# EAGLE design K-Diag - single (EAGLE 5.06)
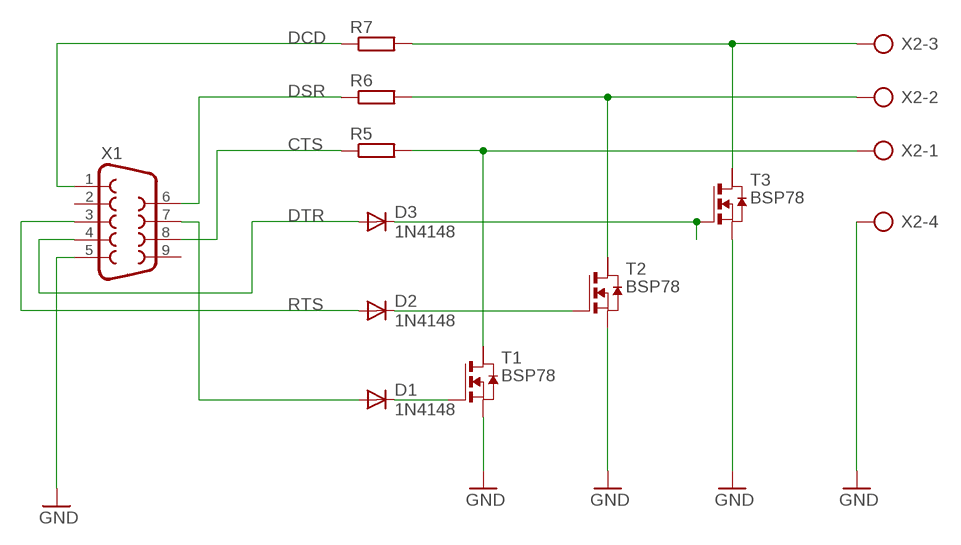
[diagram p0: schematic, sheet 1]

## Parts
D1  1N4148  1N4148DO35-7  [DO35-7]
D2  1N4148  1N4148DO35-7  [DO35-7]
D3  1N4148  1N4148DO35-7  [DO35-7]
R5  R-EU_0207/7  [0207/7]
R6  R-EU_0207/7  [0207/7]
R7  R-EU_0207/7  [0207/7]
T1  BSP78  NMOSSOT223  [SOT223]
T2  BSP78  NMOSSOT223  [SOT223]
T3  BSP78  NMOSSOT223  [SOT223]
X1  DB9FEMALE  [DB9]
X2  AK500/4  [AK500/4]

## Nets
CTS: R5.1 X1.8
DCD: R7.1 X1.1
DSR: R6.1 X1.6
DTR: D3.A X1.4
GND: T1.3(S) T2.3(S) T3.3(S) X1.5 X2.4
N$1: D3.C T3.1(G)
N$2: D2.C T2.1(G)
N$3: D1.C T1.1(G)
N$4: R5.2 T1.2(D) X2.1
N$5: R6.2 T2.2(D) X2.2
N$6: R7.2 T3.2(D) X2.3
N$7: D1.A X1.7
RTS: D2.A X1.3
Unconnected: T1.4(D2) T2.4(D2) T3.4(D2) X1.2 X1.9

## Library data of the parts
D1-D3 = diode:1N4148: DIODE
R5-R7 = rcl:R-EU_: RESISTOR, European symbol
T1-T3 = zetex:NMOSSOT223: MOS FET
X1 = SparkFun:DB9: DB9 Connector Standard DB9 (D-Sub 9) serial connector. Can be used for CAN bus as well as RS485 and RS232. Footprint production proven. Spark Fun Electronics SKU : PRT-00429
X2 = con-ptr500:AK500/4: CONNECTOR

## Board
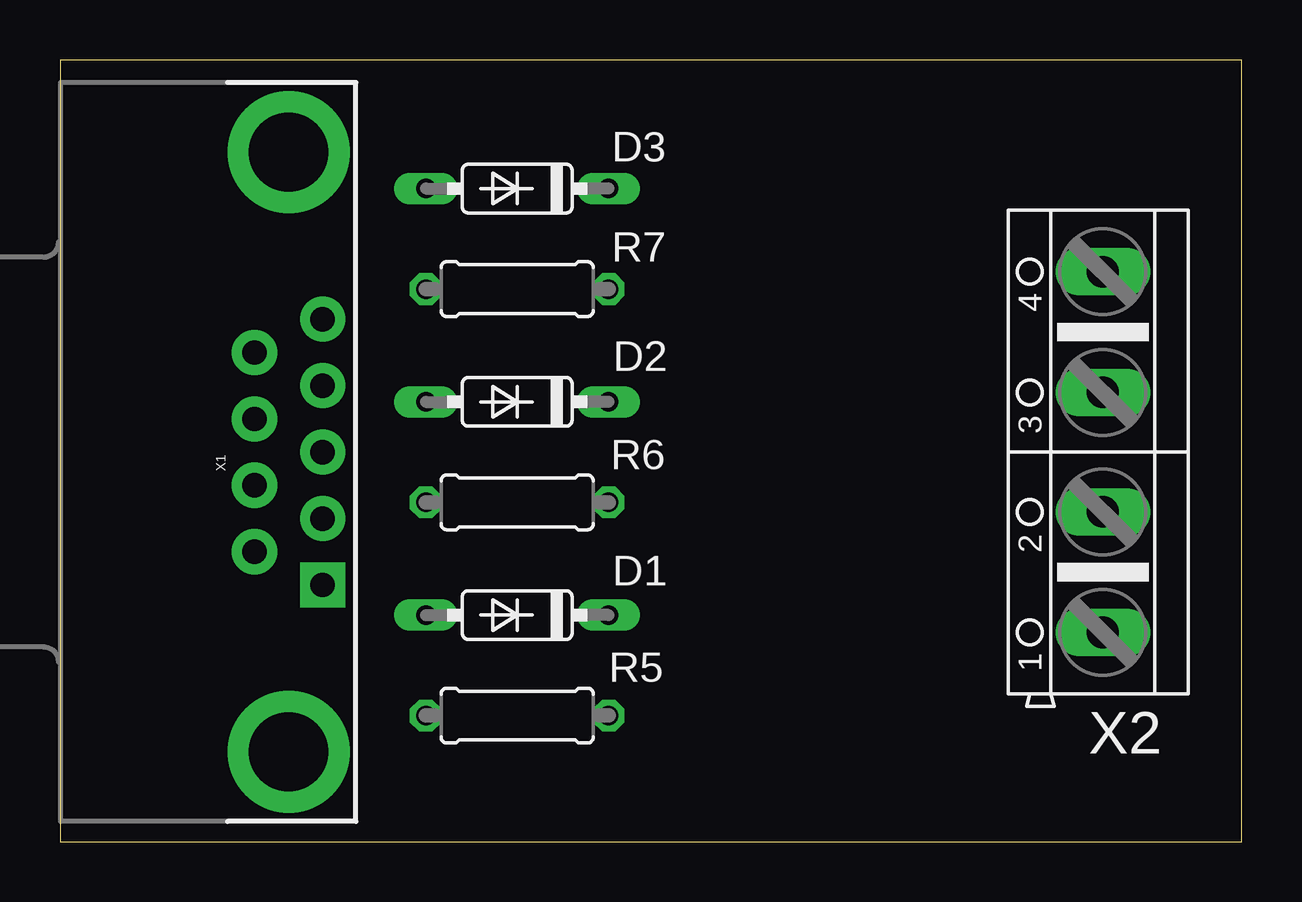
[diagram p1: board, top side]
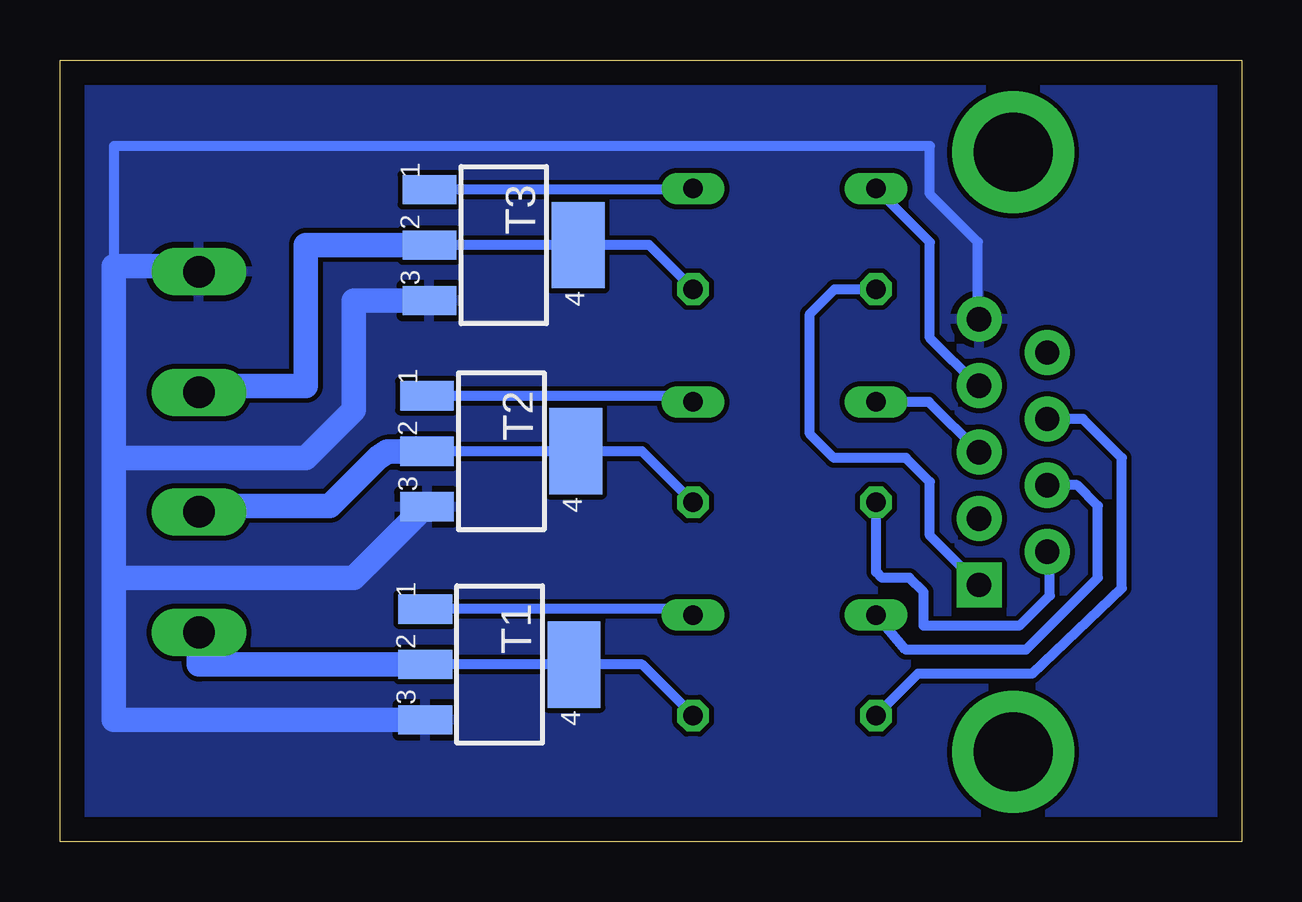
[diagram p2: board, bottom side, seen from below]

Size 49.24 x 32.59 mm. Coordinates in mm from the lower left corner, seen from the top.
Outline: 0,0 49.24,0 49.24,32.59 0,32.59 0,0
Copper layers (1*16): Top 0.035mm / dielectric 1.5mm / Bottom 0.035mm
Design rules "default": minimum track width 10mil, minimum drill 24mil, track to track 8mil, track to pad 8mil, pad to pad 8mil, via to via 8mil, smd to smd 8mil, copper to edge 40mil, drill to drill 8mil, minimum pad ring 10mil, minimum via ring 8mil, stop-mask expansion 4mil, vias tented up to drill 0mil, thermal gap 10mil

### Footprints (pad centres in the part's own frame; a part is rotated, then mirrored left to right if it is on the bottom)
DO35-7 = drill 0.813 long: A 3.81,0; C -3.81,0
0207/7 = drill 0.813 octagon: 1 -3.81,0; 2 3.81,0
SOT223 = smd 1.219 x 2.235: 1 -2.311,-3.099; 2 0,-3.099; 3 2.311,-3.099 | smd 3.6 x 2.2: 4 0,3.099
DB9 = drill 1.016 pad 1.88 square: 1 -5.54,-1.42 | drill 1.016 pad 1.88 round: 2 -2.77,-1.42; 3 0,-1.42; 4 2.77,-1.42; 5 5.54,-1.42; 6 -4.15,1.42; 7 -1.38,1.42; 8 1.38,1.42; 9 4.15,1.42 | drill 3.302 pad 5.08 round: G1 -12.5,0; G2 12.5,0
AK500/4 = drill 1.321 long: 1 -7.518,0; 2 -2.489,0; 3 2.489,0; 4 7.518,0

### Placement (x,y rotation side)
D1  19.05,9.45 180 top
D2  19.05,18.34 180 top
D3  19.05,27.23 180 top
R5  19.05,5.25 0 top
R6  19.05,14.14 0 top
R7  19.05,23.04 0 top
T1  30.92,7.38 270 bottom
T2  30.85,16.27 270 bottom
T3  30.75,24.87 270 bottom
X1  9.53,16.24 90 top
X2  43.45,16.24 90 top

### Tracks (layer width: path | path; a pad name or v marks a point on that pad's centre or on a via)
CTS
  Bottom 0.406: X1.8 6.62,17.62 5,16 5,10.57 8.74,7 13.49,7 R5.1
DCD
  Bottom 0.406: X1.1 13,12.76 13,15 14,16 17,16 18,17 18,22 16.96,23.04 R7.1
DSR
  Bottom 0.406: X1.6 8,11.98 8,10.26 9.28,9 13.26,9 13.26,10.41 13.85,11 15,11 15.24,11.24 R6.1 15.1,14
DTR
  Bottom 0.406: X1.4 11.01,19.01 13,21 13,24.98 D3.A
GND
  Bottom 0.406: X1.5 11,21.78 11,25 13,27 13,29 47,29 47,24
  Bottom 1.016: T3.3 37,22.56 37,18 39,16 47,16 | 47,16 47,24 43.69,24 X2.4 | 47,16 47,11 | T1.3 47,5.07 47,11 | T2.3 34.04,13.96 37,11 47,11
  pour Bottom: 0,33.47 50.25,33.47 50.25,-1.04 -0.95,-2.04 -0.95,33.57
N$1
  Bottom 0.406: D3.C 22.9,27.18 T3.1
N$2
  Bottom 0.406: D2.C 23.11,18.59 T2.1
N$3
  Bottom 0.406: D1.C 23.11,9.7 T1.1
N$4
  Bottom 0.406: R5.2 24.99,7.38 T1.2
  Bottom 1.016: T1.2 43.45,7.38 X2.1
N$5
  Bottom 0.406: R6.2 24.99,16.27 T2.2
  Bottom 1.016: X2.2 43.45,14 38,14 36,16 35.6,16.26 T2.2
N$6
  Bottom 0.406: R7.2 24.7,24.87 T3.2
  Bottom 1.016: T3.2 39,24.87 39,19 43.45,19 X2.3
N$7
  Bottom 0.406: X1.7 6.86,14.86 6,14 6,11 9,8 14,8 D1.A
RTS
  Bottom 0.406: X1.3 13.04,18.34 D2.A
